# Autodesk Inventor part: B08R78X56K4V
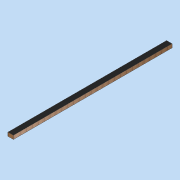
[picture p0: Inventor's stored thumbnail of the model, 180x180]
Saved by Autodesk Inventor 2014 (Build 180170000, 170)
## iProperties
Created: 2011-08
Part Number: B08R78X56K4V
Document SubType Name: Modeling
Designer: david.appleford
Density: 0.435625 g/cm^3
Description: Roof Edge Beam 2w - 4 Locks
Mass: 5000 g
Surface Area: 6926.08 cm^2
Volume: 11477.8 cm^3
Cost Center: £27.00
Material: 000 Redwood
Appearance: Wood (Oak)
Justset: False
Title: Roof Edge Beam 2w - 4 Locks
Author: david.appleford
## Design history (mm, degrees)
sketch "Sketch1"
  geometry: L1 (39, -34)-(-39, -34); L2 (-39, -34)-(-39, 2406); L3 (-39, 2406)-(39, 2406); L4 (39, 2406)-(39, -34); 1 further point
  constraints: 8 end point, 2 parallel, 1 horizontal, 1 perpendicular, 1 other
  dimensions: "d2" = 78 distance between parallel lines of L2 L4; "d3" = 34 distance from line of point (0, 0) L1; "d4" = 39 distance from line of point (0, 0) L2 (= 0.5 x d2); "d5" = 2440 distance of L3.end L1.start
extrude "Extrusion1" new body sketch "Sketch1" distance "d0" = 56; taper "d1" = 0 deg
feature "Move Face1" dims "d6" = 6
body "Solid1"
